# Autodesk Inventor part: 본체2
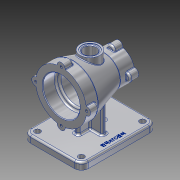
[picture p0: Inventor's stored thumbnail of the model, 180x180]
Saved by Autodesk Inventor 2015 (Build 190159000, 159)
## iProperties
Created: 2020-12
Part Number: 본체2
Material: 알루미늄 6061
Document SubType Name: Modeling
Designer: Lineart
Density: 2.7 g/cm^3
Appearance: 알루미늄 - 평지
Mass: 1032.82 g
Surface Area: 850.64 cm^2
Volume: 382.527 cm^3
Author: Lineart
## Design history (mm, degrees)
sketch "스케치1"
  geometry: L1 (-50, 0)-(50, 0); L2 (-50, 0)-(-50, 44); L3 (-50, 44)-(-30, 44); L4 (-30, 44)-(25, 27.5); L5 (25, 27.5)-(50, 27.5); L6 (50, 27.5)-(50, 0); 2 further points
  constraints: 12 end point, 2 perpendicular, 1 coincident, 1 horizontal, 1 midpoint, 1 parallel, 1 vertical
  dimensions: "d1" = 88 diameter of L3 L1; "d2" = 55 diameter of L5 L1; "d4" = 100 distance between parallel lines of L6 L2; "d5" = 20 distance from line of L3.end L2; "d158" = 25 distance from line of L4.end L6
revolve "회전1" sketch "스케치1" stored, may be unused: angle "d7" = 90 deg
node "작업 평면1"
node "작업 평면2"
sketch "스케치3"
  geometry: L1 (-65, -50)-(65, -50); L2 (65, -50)-(65, 50); L3 (65, 50)-(-65, 50); L4 (-65, 50)-(-65, -50); L5 (-65, -50)-(65, 50); L6 (65, -50)-(-65, 50); 1 further point
  constraints: 12 end point, 2 midpoint, 2 parallel, 1 horizontal, 1 perpendicular
  dimensions: "d9" = 130 distance of L3.end L2.end; "d10" = 100 distance of L2.end L1.end
extrude "돌출1" join sketch "스케치3" distance "d11" = 12; taper "d12" = 0 deg
sketch "스케치5"
  geometry: L1 (0, -4)-(0, 4); L2 (24, 0)-(-24, 0); L3 (-65, -50)-(-65, 50) reference; L4 (65, -50)-(-65, -50) reference; L5 (24, -4)-(24, 4); L6 (-24, -4)-(-24, 4); L7 (24, -4)-(-24, -4); L8 (24, 4)-(-24, 4); 1 further point
  constraints: 12 end point, 4 midpoint, 4 parallel
  dimensions: "d15" = 65 distance between parallel lines of L3 L1; "d16" = 50 distance between parallel lines of L2 L4; "d17" = 24 distance between parallel lines of L1 L5; "d18" = 24 distance between parallel lines of L1 L6; "d19" = 4 distance between parallel lines of L2 L7; "d20" = 4 distance between parallel lines of L2 L8
extrude "돌출2" join sketch "스케치5" distance "d21" = 67.5; taper "d22" = 0 deg
node "작업 평면4"
sketch "스케치6"
  geometry: L1 (-62.176, 4)-(12, 4); L2 (-62.176, -21)-(12, -21); L3 (-62.176, 29)-(12, 29); L4 (12, -46)-(12, 54) reference; L5 (-62.176, -21)-(-62.176, 29); L6 (12, -21)-(12, 29); 1 further point
  constraints: 10 end point, 2 midpoint, 2 parallel, 2 point on line, 1 collinear, 1 horizontal, 1 vertical
  dimensions: "d23" = 25 distance between parallel lines of L1 L2; "d24" = 25 distance between parallel lines of L1 L3; "d25" = 50 distance of L3.end L2.end (derived); "d26" = 74.17552 distance between parallel lines of L4 L5; "d27" = 25 distance from line of L4.end L3
extrude "돌출3" join sketch "스케치6" stored distance "d28" = 8; taper "d29" = 0 deg
sketch "스케치7"
  geometry: L1 (50, 0)-(-50, 0); L2 (50, 44)-(50, -44) reference; L3 (50, 0)-(50, -32); L4 (50, -32)-(30, -32); L5 (27, -29)-(27, -29); L6 (24, -26)-(-17, -26); L7 (-20, -23)-(-20, -23); L8 (-50, 27.5)-(-50, -27.5) reference; L9 (-23, -20)-(-50, -20); L10 (-50, -20)-(-50, 0); A1 r 3 centre (30, -29) between (27, -29) and (30, -32); A2 r 3 centre (24, -29) between (27, -29) and (24, -26); A3 r 3 centre (-17, -23) between (-20, -23) and (-17, -26); A4 r 3 centre (-23, -23) between (-20, -23) and (-23, -20); 1 further point
  constraints: 16 end point, 8 point on circle, 8 tangent, 4 centre point, 4 perpendicular, 3 equal radius, 2 horizontal, 2 midpoint, 2 point on line
  dimensions: "d30" = 64 diameter of L4 L1; "d31" = 52 diameter of L6 L1; "d33" = 23 distance between parallel lines of L5 L2; "d34" = 47 distance between parallel lines of L7 L5; "d36" = 40 diameter of L9 L1; "d37" = 30 distance between parallel lines of L8 L7 (derived); "d38" = 3 radius of A1
revolve "회전2" sketch "스케치7" stored, may be unused: angle "d39" = 90 deg
sketch "스케치8"
  geometry: C1 r 7 at (-44, 0); C2 r 7 at (0, -44); C3 r 7 at (44, 0); C4 r 7 at (0, 44); A1 r 44 centre (0, 0) between (-44, 0) and (0, 44) reference; 3 further points
  constraints: 4 centre point, 4 coincident, 4 point on circle, 2 horizontal alignment, 2 vertical alignment
  dimensions: "d40" = 7 radius of C1; "d41" = 7 radius of C2; "d42" = 7 radius of C3; "d45" = 7 radius of C4
extrude "돌출4" join sketch "스케치8" distance "d46" = 15; taper "d47" = 0 deg
sketch "스케치9"
  geometry: C1 r 7 at (27.5, 0); C2 r 7 at (0, 27.5); C3 r 7 at (-27.5, 0); C4 r 7 at (0, -27.5); A1 r 27.5 centre (0, 0) between (27.5, 0) and (0, 27.5) reference; A2 r 27.5 centre (0, 0) between (27.5, 0) and (0, 27.5) reference; 3 further points
  constraints: 8 point on circle, 4 centre point, 4 coincident, 2 horizontal alignment, 2 vertical alignment
  dimensions: "d48" = 7 radius of C1; "d49" = 7 radius of C2; "d50" = 7 radius of C3; "d51" = 7 radius of C4
extrude "돌출5" join sketch "스케치9" distance "d52" = 15; taper "d53" = 0 deg
hole "구멍1" diameter "d56" = 4.134; stored, may be unused: countersink angle "d60" = 90 deg, drill point angle "d62" = 118 deg; dims "d54" = 10, "d55" = 10, "d57" = 9, "d58" = 4, "d59" = 2, "d61" = 11
hole "구멍2" diameter "d65" = 4.134; stored, may be unused: countersink angle "d69" = 90 deg, drill point angle "d71" = 118 deg; dims "d63" = 10, "d64" = 10, "d66" = 9, "d67" = 4, "d68" = 2, "d70" = 11
hole "구멍3" diameter "d74" = 4.134; stored, may be unused: countersink angle "d78" = 90 deg, drill point angle "d80" = 118 deg; dims "d72" = 10, "d73" = 10, "d75" = 9, "d76" = 4, "d77" = 2, "d79" = 11
hole "구멍4" diameter "d83" = 4.134; stored, may be unused: countersink angle "d87" = 90 deg, drill point angle "d89" = 118 deg; dims "d81" = 10, "d82" = 10, "d84" = 9, "d85" = 4, "d86" = 2, "d88" = 11
hole "구멍5" diameter "d92" = 4.134; stored, may be unused: countersink angle "d96" = 90 deg, drill point angle "d98" = 118 deg; dims "d90" = 10, "d91" = 10, "d93" = 9, "d94" = 4, "d95" = 2, "d97" = 11
hole "구멍6" diameter "d101" = 4.134; stored, may be unused: countersink angle "d105" = 90 deg, drill point angle "d107" = 118 deg; dims "d99" = 10, "d100" = 10, "d102" = 9, "d103" = 4, "d104" = 2, "d106" = 11
hole "구멍7" diameter "d110" = 4.134; stored, may be unused: countersink angle "d114" = 90 deg, drill point angle "d116" = 118 deg; dims "d108" = 10, "d109" = 10, "d111" = 9, "d112" = 4, "d113" = 2, "d115" = 11
hole "구멍8" diameter "d119" = 4.134; stored, may be unused: countersink angle "d123" = 90 deg, drill point angle "d125" = 118 deg; dims "d117" = 10, "d118" = 10, "d120" = 9, "d121" = 4, "d122" = 2, "d124" = 11
fillet "모깎기1" dims "d126" = 12
fillet "모깎기2" dims "d127" = 3
sketch "스케치11"
  geometry: C1 r 5 at (53, -38); C2 r 5 at (53, 38); C3 r 5 at (-53, 38); C4 r 5 at (-53, -38); A1 r 12 centre (53, -38) between (53, -50) and (65, -38) reference; A2 r 12 centre (53, 38) between (65, 38) and (53, 50) reference; A3 r 12 centre (-53, 38) between (-53, 50) and (-65, 38) reference; A4 r 12 centre (-53, -38) between (-65, -38) and (-53, -50) reference; 1 further point
  constraints: 4 centre point, 4 coincident
  dimensions: "d128" = 10 diameter of C1; "d129" = 10 diameter of C2; "d130" = 10 diameter of C3; "d131" = 10 diameter of C4
extrude "돌출6" cut sketch "스케치11" stored distance "d132" = 15; taper "d133" = 0 deg
fillet "모깎기3" dims "d134" = 3
fillet "모깎기4" dims "d135" = 3
fillet "모깎기5" dims "d136" = 3
fillet "모깎기6" dims "d137" = 3
node "작업 평면5"
sketch "스케치13"
  geometry: C1 r 17 at (0, 0); 1 further point
  constraints: 1 centre point, 1 coincident
  dimensions: "d139" = 34 diameter of C1
extrude "돌출7" join sketch "스케치13" distance "d140" = 18.25; taper "d141" = 0 deg
sketch "스케치14"
  geometry: C1 r 14 at (0, 0); 1 further point
  constraints: 1 centre point, 1 coincident
  dimensions: "d142" = 28 diameter of C1
extrude "돌출8" cut sketch "스케치14" distance "d143" = 1; taper "d144" = 0 deg
sketch "스케치15"
  geometry: C1 r 11 at (0, 0); 1 further point
  constraints: 1 centre point, 1 coincident
  dimensions: "d145" = 22 diameter of C1
extrude "돌출9" cut sketch "스케치15" distance "d146" = 36; taper "d147" = 0 deg
fillet "모깎기7" dims "d148" = 3
fillet "모깎기8" dims "d149" = 1
fillet "모깎기9" dims "d150" = 1
chamfer "모따기1" distance "d151" = 1; stored, may be unused: second distance "d152" = 2, angle "d153" = 45 deg
fillet "모깎기10" dims "d154" = 1
sketch "스케치16"
  geometry: L1 (53, 50)-(-53, 50) reference; 2 further points
  constraints: 1 vertical alignment, 1 other
  dimensions: "d155" = 10 vertical distance of L1.start point (0, 40)
feature "엠보싱1" sketch "스케치16" dims "d156" = 0.5, "d157" = 0
node "솔리드1"
